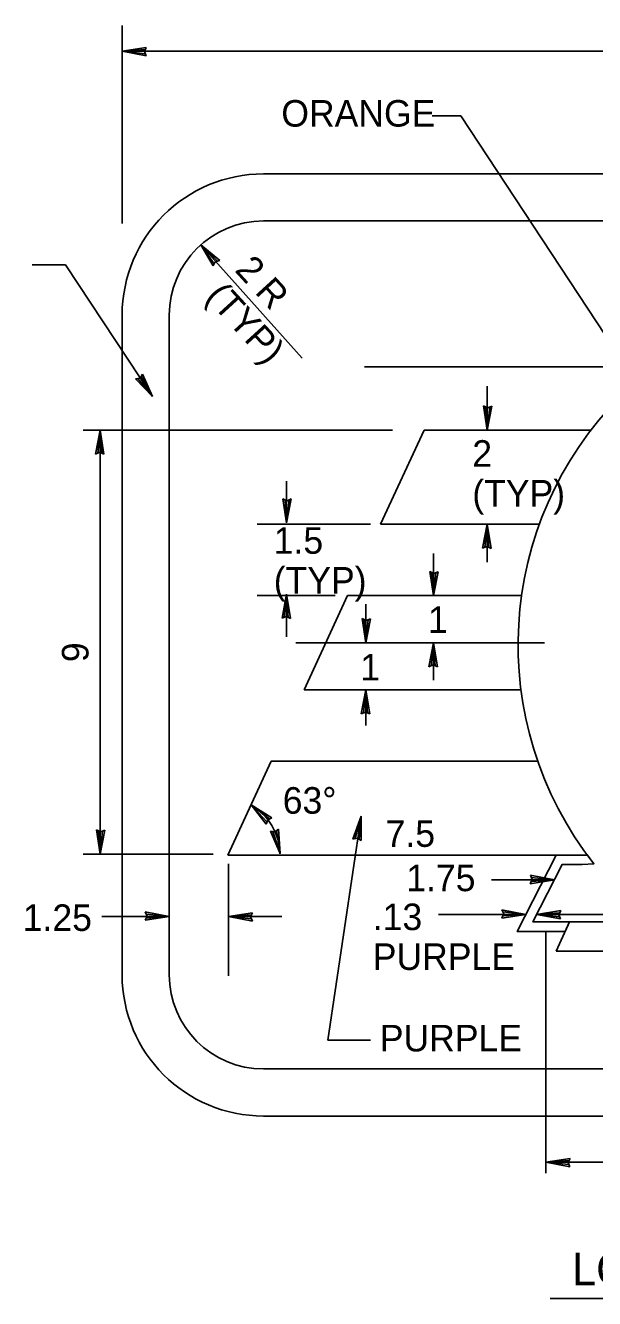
# Model space of a CAD drawing. Extents: x 10268197 to 10269179, y 2141503 to 2142677.
# Drawn here: x 10268653.32 to 10268668.41, y 2142131.77 to 2142165.55 of the extents above; entities that cross this region are included whole.
import ezdxf

# ---------------------------------------------------------------- set-up
doc = ezdxf.new("R2010")
doc.units = 0
for name, color, linetype in [('1', 7, 'Continuous'), ('21', 7, 'Continuous'), ('Default', 7, 'Continuous'), ('TextMisc', 7, 'Continuous'), ('TextShtNo', 7, 'Continuous')]:
    doc.layers.add(name, color=color, linetype=linetype)

msp = doc.modelspace()

# ---------------------------------------------------------------- linework, layer by layer
at = {"layer": '1'}
for p, q in [((10268657.967, 2142159.723), (10268660.652, 2142156.715)), ((10268662.224, 2142144.564), (10268661.335, 2142138.625)), ((10268667.63, 2142141.503), (10268666.362, 2142141.503)), ((10268661.335, 2142138.625), (10268662.468, 2142138.625))]:
    msp.add_line(p, q, dxfattribs=at)
msp.add_ellipse((10268658.575, 2142143.547), major_axis=(0, 1.49), ratio=0.999997, start_param=4.726798, end_param=5.778675, dxfattribs=at)
at = {"layer": '21'}
msp.add_line((10268667.229, 2142131.765), (10268677.069, 2142131.765), dxfattribs=at)
at = {"layer": 'Default'}
for p, q in [((10268655.882, 2142164.861), (10268656.521, 2142164.962)), ((10268655.882, 2142164.861), (10268656.494, 2142164.904)), ((10268655.882, 2142164.861), (10268688.382, 2142164.861)), ((10268655.882, 2142164.861), (10268656.517, 2142164.738)), ((10268655.882, 2142164.861), (10268656.493, 2142164.797)), ((10268656.471, 2142164.851), (10268656.521, 2142164.962)), ((10268656.517, 2142164.738), (10268656.471, 2142164.851)), ((10268664.106, 2142163.147), (10268664.863, 2142163.147)), ((10268664.863, 2142163.147), (10268669.973, 2142155.383)), ((10268659.632, 2142160.357), (10268684.632, 2142160.357)), ((10268657.967, 2142159.723), (10268658.469, 2142159.313)), ((10268657.967, 2142159.723), (10268658.298, 2142159.166)), ((10268657.967, 2142159.723), (10268658.326, 2142159.223)), ((10268657.967, 2142159.723), (10268658.407, 2142159.294)), ((10268653.493, 2142159.197), (10268654.38, 2142159.197)), ((10268654.38, 2142159.197), (10268656.683, 2142155.698)), ((10268658.298, 2142159.166), (10268658.351, 2142159.276)), ((10268658.351, 2142159.276), (10268658.469, 2142159.313)), ((10268657.132, 2142140.357), (10268657.132, 2142157.857)), ((10268662.31, 2142156.491), (10268673.647, 2142156.491)), ((10268656.359, 2142156.19), (10268656.239, 2142156.169)), ((10268656.683, 2142155.698), (10268656.239, 2142156.169)), ((10268656.683, 2142155.698), (10268656.302, 2142156.18)), ((10268656.426, 2142156.292), (10268656.359, 2142156.19)), ((10268656.683, 2142155.698), (10268656.39, 2142156.239)), ((10268656.683, 2142155.698), (10268656.426, 2142156.292)), ((10268665.566, 2142155.978), (10268665.566, 2142154.81)), ((10268665.566, 2142154.81), (10268665.464, 2142155.449)), ((10268665.576, 2142155.399), (10268665.464, 2142155.449)), ((10268665.566, 2142154.81), (10268665.522, 2142155.422)), ((10268665.566, 2142154.81), (10268665.689, 2142155.446)), ((10268665.566, 2142154.81), (10268665.63, 2142155.421)), ((10268665.689, 2142155.446), (10268665.576, 2142155.399)), ((10268654.846, 2142154.81), (10268663.053, 2142154.81)), ((10268655.299, 2142154.81), (10268655.176, 2142154.174)), ((10268655.299, 2142154.81), (10268655.235, 2142154.199)), ((10268655.299, 2142154.81), (10268655.299, 2142143.56)), ((10268655.299, 2142154.81), (10268655.4, 2142154.171)), ((10268655.299, 2142154.81), (10268655.342, 2142154.197)), ((10268663.89, 2142154.81), (10268662.736, 2142152.31)), ((10268668.316, 2142154.81), (10268663.89, 2142154.81)), ((10268655.176, 2142154.174), (10268655.289, 2142154.221)), ((10268655.289, 2142154.221), (10268655.4, 2142154.171)), ((10268660.245, 2142153.455), (10268660.245, 2142152.346)), ((10268660.245, 2142152.346), (10268660.144, 2142152.986)), ((10268660.255, 2142152.935), (10268660.144, 2142152.986)), ((10268660.245, 2142152.346), (10268660.368, 2142152.982)), ((10268660.368, 2142152.982), (10268660.255, 2142152.935)), ((10268660.245, 2142152.346), (10268660.202, 2142152.958)), ((10268660.245, 2142152.346), (10268660.309, 2142152.957)), ((10268659.465, 2142152.31), (10268662.471, 2142152.31)), ((10268666.946, 2142152.31), (10268662.736, 2142152.31)), ((10268665.566, 2142152.31), (10268665.442, 2142151.674)), ((10268665.566, 2142152.31), (10268665.502, 2142151.699)), ((10268665.566, 2142152.31), (10268665.566, 2142151.305)), ((10268665.566, 2142152.31), (10268665.667, 2142151.67)), ((10268665.566, 2142152.31), (10268665.609, 2142151.697)), ((10268665.442, 2142151.674), (10268665.555, 2142151.721)), ((10268665.555, 2142151.721), (10268665.667, 2142151.67)), ((10268664.141, 2142151.532), (10268664.141, 2142150.416)), ((10268664.141, 2142150.416), (10268664.04, 2142151.056)), ((10268664.151, 2142151.005), (10268664.04, 2142151.056)), ((10268664.141, 2142150.416), (10268664.098, 2142151.029)), ((10268664.141, 2142150.416), (10268664.264, 2142151.052)), ((10268664.141, 2142150.416), (10268664.205, 2142151.027)), ((10268664.264, 2142151.052), (10268664.151, 2142151.005)), ((10268659.465, 2142150.416), (10268661.532, 2142150.416)), ((10268660.245, 2142150.451), (10268660.122, 2142149.815)), ((10268660.245, 2142150.451), (10268660.181, 2142149.84)), ((10268660.245, 2142150.451), (10268660.245, 2142149.321)), ((10268660.245, 2142150.451), (10268660.346, 2142149.812)), ((10268660.245, 2142150.451), (10268660.288, 2142149.839)), ((10268661.861, 2142150.416), (10268660.706, 2142147.916)), ((10268666.474, 2142150.416), (10268661.861, 2142150.416)), ((10268662.346, 2142150.193), (10268662.346, 2142149.166)), ((10268660.122, 2142149.815), (10268660.235, 2142149.862)), ((10268660.235, 2142149.862), (10268660.346, 2142149.812)), ((10268662.346, 2142149.166), (10268662.245, 2142149.806)), ((10268662.356, 2142149.755), (10268662.245, 2142149.806)), ((10268662.346, 2142149.166), (10268662.303, 2142149.778)), ((10268662.346, 2142149.166), (10268662.469, 2142149.802)), ((10268662.346, 2142149.166), (10268662.41, 2142149.777)), ((10268662.469, 2142149.802), (10268662.356, 2142149.755)), ((10268660.486, 2142149.166), (10268667.084, 2142149.166)), ((10268664.141, 2142149.166), (10268664.018, 2142148.531)), ((10268664.141, 2142149.166), (10268664.078, 2142148.555)), ((10268664.141, 2142149.166), (10268664.141, 2142148.17)), ((10268664.141, 2142149.166), (10268664.242, 2142148.527)), ((10268664.141, 2142149.166), (10268664.184, 2142148.554)), ((10268664.018, 2142148.531), (10268664.131, 2142148.577)), ((10268664.131, 2142148.577), (10268664.242, 2142148.527)), ((10268666.458, 2142147.916), (10268660.706, 2142147.916)), ((10268662.346, 2142147.916), (10268662.223, 2142147.281)), ((10268662.346, 2142147.916), (10268662.283, 2142147.305)), ((10268662.346, 2142147.916), (10268662.346, 2142146.972)), ((10268662.346, 2142147.916), (10268662.448, 2142147.277)), ((10268662.346, 2142147.916), (10268662.389, 2142147.303)), ((10268662.223, 2142147.281), (10268662.336, 2142147.328)), ((10268662.336, 2142147.328), (10268662.448, 2142147.277)), ((10268659.831, 2142146.021), (10268658.681, 2142143.532)), ((10268666.88, 2142146.021), (10268659.831, 2142146.021)), ((10268659.304, 2142144.862), (10268659.853, 2142144.519)), ((10268659.304, 2142144.862), (10268659.703, 2142144.352)), ((10268659.304, 2142144.862), (10268659.723, 2142144.413)), ((10268659.304, 2142144.862), (10268659.794, 2142144.493)), ((10268659.742, 2142144.468), (10268659.853, 2142144.519)), ((10268662.224, 2142144.564), (10268661.998, 2142143.956)), ((10268662.224, 2142144.564), (10268662.062, 2142143.971)), ((10268662.224, 2142144.564), (10268662.166, 2142143.952)), ((10268662.224, 2142144.564), (10268662.22, 2142143.916)), ((10268655.299, 2142143.56), (10268655.198, 2142144.199)), ((10268655.309, 2142144.149), (10268655.198, 2142144.199)), ((10268655.299, 2142143.56), (10268655.422, 2142144.196)), ((10268655.422, 2142144.196), (10268655.309, 2142144.149)), ((10268659.703, 2142144.352), (10268659.742, 2142144.468)), ((10268660.032, 2142144.219), (10268659.935, 2142144.145)), ((10268660.075, 2142143.573), (10268659.98, 2142144.18)), ((10268660.075, 2142143.573), (10268660.032, 2142144.219)), ((10268655.299, 2142143.56), (10268655.256, 2142144.172)), ((10268655.299, 2142143.56), (10268655.363, 2142144.171)), ((10268660.075, 2142143.573), (10268659.813, 2142144.165)), ((10268659.935, 2142144.145), (10268659.813, 2142144.165)), ((10268660.075, 2142143.573), (10268659.877, 2142144.154)), ((10268661.998, 2142143.956), (10268662.117, 2142143.984)), ((10268662.117, 2142143.984), (10268662.22, 2142143.916)), ((10268654.846, 2142143.56), (10268658.295, 2142143.56)), ((10268658.681, 2142143.532), (10268668.199, 2142143.532)), ((10268667.394, 2142143.532), (10268666.362, 2142141.503)), ((10268667.394, 2142143.532), (10268668.223, 2142143.532)), ((10268658.7, 2142143.296), (10268658.7, 2142140.332)), ((10268667.55, 2142143.278), (10268666.776, 2142141.757)), ((10268667.55, 2142143.278), (10268668.083, 2142143.278)), ((10268668.083, 2142143.278), (10268668.395, 2142143.303)), ((10268665.676, 2142142.874), (10268667.344, 2142142.874)), ((10268666.755, 2142142.884), (10268666.705, 2142142.772)), ((10268667.344, 2142142.874), (10268666.705, 2142142.772)), ((10268667.344, 2142142.874), (10268666.708, 2142142.997)), ((10268666.708, 2142142.997), (10268666.755, 2142142.884)), ((10268667.344, 2142142.874), (10268666.732, 2142142.83)), ((10268667.344, 2142142.874), (10268666.733, 2142142.937)), ((10268655.342, 2142141.901), (10268657.132, 2142141.901)), ((10268656.543, 2142141.911), (10268656.492, 2142141.801)), ((10268657.132, 2142141.901), (10268656.492, 2142141.801)), ((10268657.132, 2142141.901), (10268656.496, 2142142.025)), ((10268656.496, 2142142.025), (10268656.543, 2142141.911)), ((10268657.132, 2142141.901), (10268656.52, 2142141.859)), ((10268657.132, 2142141.901), (10268656.521, 2142141.965)), ((10268658.7, 2142141.901), (10268659.339, 2142142.003)), ((10268658.7, 2142141.901), (10268659.312, 2142141.945)), ((10268658.7, 2142141.901), (10268660.116, 2142141.901)), ((10268658.7, 2142141.901), (10268659.336, 2142141.779)), ((10268658.7, 2142141.901), (10268659.311, 2142141.838)), ((10268659.289, 2142141.892), (10268659.339, 2142142.003)), ((10268659.336, 2142141.779), (10268659.289, 2142141.892)), ((10268664.27, 2142141.959), (10268666.589, 2142141.959)), ((10268666, 2142141.969), (10268665.95, 2142141.858)), ((10268666.589, 2142141.959), (10268665.95, 2142141.858)), ((10268666.589, 2142141.959), (10268665.953, 2142142.082)), ((10268665.953, 2142142.082), (10268666, 2142141.969)), ((10268666.589, 2142141.959), (10268665.977, 2142141.916)), ((10268666.589, 2142141.959), (10268665.978, 2142142.023)), ((10268666.874, 2142141.959), (10268667.513, 2142142.06)), ((10268666.874, 2142141.959), (10268667.486, 2142142.002)), ((10268666.874, 2142141.959), (10268668.781, 2142141.959)), ((10268666.874, 2142141.959), (10268667.509, 2142141.836)), ((10268666.874, 2142141.959), (10268667.485, 2142141.895)), ((10268667.462, 2142141.949), (10268667.513, 2142142.06)), ((10268667.509, 2142141.836), (10268667.462, 2142141.949)), ((10268666.776, 2142141.757), (10268667.87, 2142141.757)), ((10268667.12, 2142135.093), (10268667.12, 2142141.515)), ((10268667.389, 2142140.981), (10268667.747, 2142141.757)), ((10268678.995, 2142141.757), (10268667.747, 2142141.757)), ((10268679.689, 2142140.981), (10268667.389, 2142140.981)), ((10268659.632, 2142137.857), (10268684.632, 2142137.857)), ((10268667.12, 2142135.383), (10268667.76, 2142135.484)), ((10268667.12, 2142135.383), (10268667.733, 2142135.426)), ((10268667.709, 2142135.373), (10268667.76, 2142135.484)), ((10268667.12, 2142135.383), (10268678.995, 2142135.383)), ((10268667.12, 2142135.383), (10268667.756, 2142135.26)), ((10268667.12, 2142135.383), (10268667.732, 2142135.319)), ((10268667.756, 2142135.26), (10268667.709, 2142135.373))]:
    msp.add_line(p, q, dxfattribs=at)
for centre, major_axis, start_param, end_param in [((10268659.632, 2142157.857), (0, 2.5), 0, 1.570796), ((10268675.757, 2142149.107), (0, 9.375), 5.619293, 8.52162), ((10268659.632, 2142140.357), (0, -2.5), 4.712389, 6.283185)]:
    msp.add_ellipse(centre, major_axis=major_axis, ratio=0.999997, start_param=start_param, end_param=end_param, dxfattribs=at)
at = {"layer": 'TextMisc'}
for p, q in [((10268655.882, 2142160.287), (10268655.882, 2142165.546)), ((10268659.632, 2142161.607), (10268684.632, 2142161.607)), ((10268655.882, 2142140.357), (10268655.882, 2142157.857)), ((10268659.632, 2142136.607), (10268684.632, 2142136.607))]:
    msp.add_line(p, q, dxfattribs=at)
for centre, major_axis, start_param, end_param in [((10268659.632, 2142157.857), (0, 3.75), 0, 1.570796), ((10268659.632, 2142140.357), (0, -3.75), 4.712389, 6.283185)]:
    msp.add_ellipse(centre, major_axis=major_axis, ratio=0.999998, start_param=start_param, end_param=end_param, dxfattribs=at)
at = {"layer": 'TextShtNo'}
for p, q in [((10268667.389, 2142140.981), (10268667.747, 2142141.757)), ((10268667.747, 2142141.757), (10268678.995, 2142141.757)), ((10268679.689, 2142140.981), (10268667.389, 2142140.981))]:
    msp.add_line(p, q, dxfattribs=at)
msp.add_lwpolyline([(10268668.223, 2142143.532), (10268667.394, 2142143.532), (10268666.362, 2142141.503), (10268667.63, 2142141.503), (10268667.747, 2142141.757), (10268666.776, 2142141.757), (10268667.55, 2142143.278), (10268668.083, 2142143.278), (10268668.395, 2142143.303)], close=True, dxfattribs=at)

# ---------------------------------------------------------------- texts
at = {"layer": '1'}
for s, height, p in [('ORANGE', 0.7047, (10268660.104, 2142162.861)), ('2', 0.705, (10268665.168, 2142153.836)), ('(TYP)', 0.7047, (10268665.168, 2142152.779)), ('1.5', 0.7047, (10268659.903, 2142151.527)), ('(TYP)', 0.7047, (10268659.903, 2142150.47)), ('1', 0.705, (10268663.994, 2142149.427)), ('1', 0.705, (10268662.201, 2142148.166)), ('63°', 0.7047, (10268660.141, 2142144.63)), ('7.5', 0.7047, (10268662.87, 2142143.75)), ('1.75', 0.7047, (10268663.418, 2142142.574)), ('1.25', 0.7047, (10268653.247, 2142141.519)), ('.13', 0.7047, (10268662.529, 2142141.541)), ('PURPLE', 0.7047, (10268662.529, 2142140.484)), ('PURPLE', 0.7047, (10268662.716, 2142138.322)), ('LOGO EP-7.5R', 0.8624, (10268667.814, 2142132.117))]:
    msp.add_text(s, height=height, dxfattribs=at).set_placement(p)
for s, height, rotation, p in [('2 R', 0.7047, 312.435, (10268658.847, 2142159.038)), ('(TYP)', 0.7047, 312.435, (10268658.067, 2142158.325)), ('9', 0.705, 90, (10268654.99, 2142148.652))]:
    msp.add_text(s, height=height, rotation=rotation, dxfattribs=at).set_placement(p)

doc.saveas('drawing.dxf')
